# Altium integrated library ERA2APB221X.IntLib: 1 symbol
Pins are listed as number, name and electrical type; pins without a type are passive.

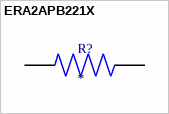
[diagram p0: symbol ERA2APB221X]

## ERA2APB221X
designator R?
MP: ERA2APB221X
footprint RES_ERA2APB221X
pins: 1, 2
